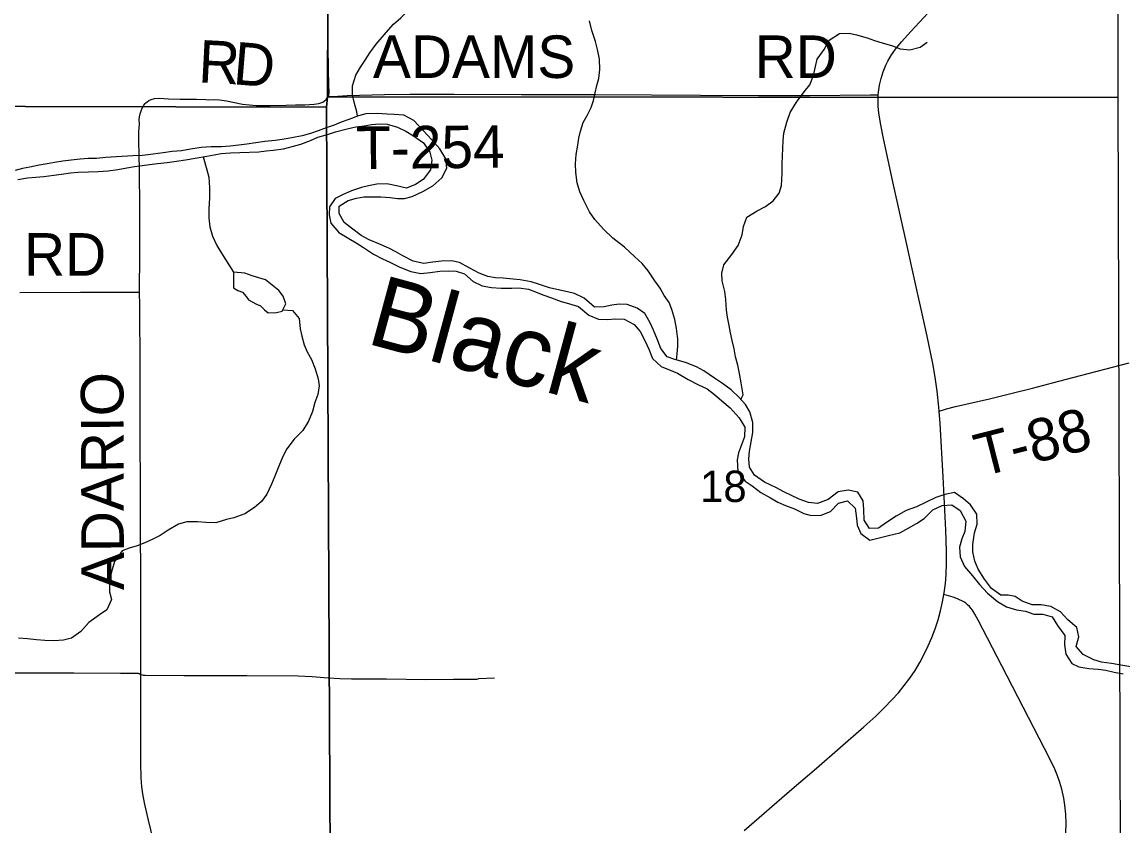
# Model space of a CAD drawing. Extents: x 0 to 70.2, y 0 to 31.4.
# Drawn here: x 4.299 to 5.768, y 15.356 to 16.429 of the extents above; entities that cross this region are included whole.
import ezdxf

# ---------------------------------------------------------------- set-up
doc = ezdxf.new("R2010")
doc.units = 0
for name, color, linetype in [('GM_X_County_Road', 7, 'Continuous'), ('GM_X_Major_River', 7, 'Continuous'), ('GM_X_Major_River_Text', 7, 'Continuous'), ('GM_X_Minor_Lake', 7, 'Continuous'), ('GM_X_Minor_River', 7, 'Continuous'), ('GM_X_Section', 7, 'Continuous'), ('GM_X_Section_Text', 7, 'Continuous'), ('GM_X_State_Route', 7, 'Continuous'), ('GM_X_Township_Road', 7, 'Continuous'), ('GM_X_Township_Road_Text', 7, 'Continuous')]:
    doc.layers.add(name, color=color, linetype=linetype)

msp = doc.modelspace()

# ---------------------------------------------------------------- linework, layer by layer
at = {"layer": 'GM_X_County_Road'}
msp.add_lwpolyline([(5.6936, 15.3452), (5.6937, 15.3577), (5.6933, 15.3701), (5.6921, 15.3825), (5.6907, 15.3916), (5.6879, 15.4038), (5.6853, 15.4128), (5.6822, 15.4216), (5.6786, 15.4303), (5.6719, 15.4443), (5.6576, 15.472), (5.6078, 15.5686), (5.5765, 15.6294), (5.5721, 15.6376), (5.5686, 15.6429), (5.5667, 15.6454), (5.5646, 15.6478), (5.5623, 15.65), (5.5598, 15.652), (5.5572, 15.6538), (5.5545, 15.6554), (5.5516, 15.6568), (5.5487, 15.658), (5.5428, 15.6601), (5.5367, 15.6618), (5.5304, 15.6636)], dxfattribs=at)
at = {"layer": 'GM_X_Major_River'}
for points in [[(5.3169, 15.8008), (5.3063, 15.8069), (5.2911, 15.8137), (5.2778, 15.8232), (5.271, 15.8338), (5.2699, 15.8452), (5.271, 15.8554), (5.2733, 15.8679), (5.2752, 15.8804), (5.2752, 15.8937), (5.2714, 15.9078), (5.2654, 15.9176), (5.2567, 15.9275), (5.2464, 15.937), (5.2347, 15.9457), (5.2241, 15.9529), (5.2101, 15.9627), (5.2002, 15.9681), (5.1854, 15.9737), (5.1714, 15.9775), (5.1608, 15.9813), (5.1525, 15.9923), (5.1479, 16.0041), (5.1426, 16.017), (5.1381, 16.0268), (5.1312, 16.039), (5.121, 16.0462), (5.1074, 16.0511), (5.0968, 16.0515), (5.0869, 16.0504), (5.077, 16.0481), (5.0638, 16.0477), (5.0501, 16.0595), (5.0372, 16.0659), (5.0278, 16.0682), (5.0134, 16.0712), (5.0039, 16.0735), (4.9891, 16.0784), (4.9792, 16.0814), (4.9648, 16.0841), (4.9554, 16.0852), (4.9417, 16.0864), (4.9319, 16.0868), (4.9213, 16.0886), (4.9099, 16.0932), (4.8966, 16.1), (4.8837, 16.1072), (4.8731, 16.1095), (4.8595, 16.1091), (4.8481, 16.1076), (4.836, 16.1061), (4.8216, 16.1091), (4.8079, 16.1163), (4.7984, 16.1216), (4.789, 16.1266), (4.7757, 16.1323), (4.7628, 16.1376), (4.7522, 16.1432), (4.7393, 16.1531), (4.7295, 16.1607), (4.7227, 16.1728), (4.7227, 16.1827), (4.7348, 16.1899), (4.7462, 16.1933), (4.756, 16.1948), (4.7655, 16.1952), (4.7784, 16.1952), (4.7909, 16.1941), (4.8008, 16.1929), (4.8102, 16.1929), (4.8205, 16.1956), (4.8345, 16.202), (4.8478, 16.2096), (4.8599, 16.2203), (4.8667, 16.2335), (4.8652, 16.2457), (4.8573, 16.2593), (4.8467, 16.2711), (4.8349, 16.2836), (4.8228, 16.2969), (4.8092, 16.3041), (4.7963, 16.3048), (4.7868, 16.3056), (4.7735, 16.3064), (4.7587, 16.306), (4.7489, 16.3033), (4.7356, 16.2984), (4.7257, 16.2946), (4.7163, 16.2908), (4.7053, 16.287), (4.6947, 16.2832), (4.6844, 16.2794), (4.6734, 16.2764), (4.6598, 16.2737), (4.6469, 16.2718), (4.6374, 16.2703), (4.6234, 16.2688), (4.5995, 16.2654), (4.5889, 16.2642), (4.5775, 16.2627), (4.5658, 16.2619)], [(4.546, 16.2494), (4.5559, 16.2513), (4.5654, 16.2528), (4.5779, 16.2536), (4.59, 16.2544), (4.6158, 16.2551), (4.6253, 16.2566), (4.6347, 16.2574), (4.6484, 16.2593), (4.6617, 16.2627), (4.6715, 16.2654), (4.6848, 16.2703), (4.6943, 16.2745), (4.7075, 16.2783), (4.7178, 16.2817), (4.7318, 16.2855), (4.7451, 16.2885), (4.7564, 16.29), (4.7659, 16.2916), (4.7769, 16.2927), (4.7872, 16.2923), (4.8008, 16.2881), (4.8118, 16.2828), (4.822, 16.2764), (4.8353, 16.2673), (4.844, 16.2548), (4.8467, 16.2438), (4.8447, 16.2309), (4.8349, 16.218), (4.825, 16.2115), (4.8129, 16.2066), (4.7996, 16.2096), (4.7864, 16.2123), (4.7731, 16.2119), (4.7621, 16.2096), (4.7526, 16.2074), (4.7393, 16.2032), (4.7272, 16.1979), (4.7174, 16.1929), (4.7101, 16.1816), (4.7094, 16.1709), (4.7117, 16.1599), (4.7226, 16.1474), (4.7359, 16.1395), (4.7458, 16.1334), (4.7552, 16.1273), (4.7689, 16.1182), (4.7806, 16.1121), (4.7905, 16.1076), (4.8041, 16.1012), (4.8185, 16.0951), (4.8318, 16.0928), (4.8443, 16.094), (4.8572, 16.0958), (4.8693, 16.0962), (4.8792, 16.0955), (4.8905, 16.0921), (4.9019, 16.0818), (4.914, 16.0761), (4.9265, 16.0739), (4.9394, 16.0731), (4.9535, 16.0731), (4.9629, 16.0735), (4.9758, 16.0716), (4.9853, 16.0682), (4.9948, 16.064), (5.0065, 16.0602), (5.0194, 16.0553), (5.0293, 16.0526), (5.0425, 16.0485), (5.0562, 16.0371), (5.0691, 16.0314), (5.0816, 16.031), (5.0911, 16.0321), (5.1036, 16.0318), (5.1168, 16.0246), (5.1248, 16.0151), (5.1312, 16.0029), (5.1365, 15.9916), (5.1415, 15.9791), (5.1528, 15.9684), (5.1649, 15.9635), (5.1748, 15.9593), (5.1888, 15.951), (5.2021, 15.9445), (5.2142, 15.9385), (5.2244, 15.9309), (5.2339, 15.9225), (5.2449, 15.9131), (5.257, 15.8998), (5.2646, 15.8873), (5.2642, 15.8744), (5.2601, 15.8638), (5.2563, 15.8531), (5.2544, 15.8437), (5.2555, 15.8281), (5.265, 15.8152), (5.2744, 15.8088), (5.2862, 15.8), (5.2991, 15.7928), (5.3089, 15.7871)], [(4.5658, 16.2619), (4.5521, 16.2619), (4.5385, 16.2608), (4.5244, 16.2585), (4.5123, 16.2566), (4.4998, 16.2555), (4.488, 16.254), (4.4744, 16.2521), (4.46, 16.2502), (4.4475, 16.2498), (4.4255, 16.2483), (4.4111, 16.2475), (4.3986, 16.2464), (4.3876, 16.246), (4.377, 16.2452), (4.3648, 16.2441), (4.3538, 16.2426), (4.3425, 16.2407), (4.333, 16.2392), (4.322, 16.2373), (4.3099, 16.2346), (4.3, 16.2327), (4.2901, 16.2301)], [(4.2936, 16.2183), (4.3068, 16.2202), (4.3178, 16.2213), (4.3284, 16.2221), (4.3417, 16.224), (4.3519, 16.2255), (4.3641, 16.227), (4.3743, 16.2278), (4.3883, 16.2282), (4.4012, 16.2289), (4.4145, 16.2297), (4.4274, 16.2316), (4.4395, 16.2339), (4.4497, 16.2354), (4.4596, 16.2369), (4.4695, 16.238), (4.4801, 16.2396), (4.493, 16.2411), (4.5055, 16.2426), (4.5176, 16.2445), (4.5305, 16.2468), (4.546, 16.2494)], [(5.7804, 15.5672), (5.7668, 15.5695), (5.7543, 15.5717), (5.741, 15.5736), (5.7308, 15.5763), (5.7164, 15.5835), (5.7073, 15.5941), (5.7107, 15.607), (5.708, 15.6195), (5.6963, 15.6298), (5.6861, 15.6408), (5.6732, 15.6476), (5.6607, 15.6499), (5.6485, 15.6499), (5.6353, 15.6548), (5.6258, 15.6612), (5.6163, 15.6628), (5.6068, 15.6628), (5.594, 15.6719), (5.5849, 15.6844), (5.5765, 15.6976), (5.572, 15.7083), (5.5693, 15.7208), (5.5693, 15.7306), (5.5716, 15.7462), (5.575, 15.7576), (5.5747, 15.7709), (5.5663, 15.7834), (5.5569, 15.7917), (5.5447, 15.8001), (5.5318, 15.7974), (5.5197, 15.7932), (5.4939, 15.7811), (5.4803, 15.7758), (5.4666, 15.7682), (5.4541, 15.7598), (5.4431, 15.7526), (5.431, 15.7519), (5.4242, 15.7629), (5.4238, 15.7773), (5.4227, 15.7887), (5.4155, 15.8004), (5.4026, 15.8031), (5.3893, 15.8008), (5.376, 15.7909), (5.3616, 15.7852), (5.3499, 15.7868), (5.3374, 15.7913), (5.3271, 15.7959), (5.3169, 15.8008)], [(5.3089, 15.7871), (5.3188, 15.7826), (5.3309, 15.778), (5.3434, 15.772), (5.3533, 15.7693), (5.3665, 15.7697), (5.379, 15.7746), (5.3897, 15.786), (5.4018, 15.789), (5.412, 15.7792), (5.4139, 15.7659), (5.4147, 15.7564), (5.4196, 15.7454), (5.4317, 15.7363), (5.4458, 15.7401), (5.4568, 15.7428), (5.4715, 15.7462), (5.4837, 15.753), (5.4939, 15.7587), (5.5042, 15.7655), (5.5159, 15.7769), (5.5284, 15.7826), (5.5413, 15.7837), (5.5523, 15.7758), (5.5599, 15.7617), (5.5587, 15.7481), (5.5546, 15.7382), (5.5515, 15.7272), (5.5523, 15.7143), (5.558, 15.7014), (5.5689, 15.6885), (5.578, 15.6772), (5.589, 15.6654), (5.6023, 15.6544), (5.6144, 15.6472), (5.6277, 15.6434), (5.6394, 15.6415), (5.6508, 15.6377), (5.6629, 15.6377), (5.6751, 15.6339), (5.6823, 15.6222), (5.6921, 15.6089), (5.6917, 15.5964), (5.6936, 15.5842), (5.7016, 15.5717), (5.711, 15.5672), (5.7243, 15.5649), (5.7364, 15.5641), (5.7467, 15.5626), (5.7581, 15.56), (5.7698, 15.5577)]]:
    msp.add_lwpolyline(points, dxfattribs=at)
at = {"layer": 'GM_X_Minor_Lake'}
for points in [[(4.5817, 16.0733), (4.5877, 16.0698), (4.5938, 16.0675), (4.5986, 16.0618), (4.602, 16.0572), (4.6126, 16.0518), (4.6179, 16.0494), (4.6231, 16.0441), (4.628, 16.0399), (4.639, 16.0405), (4.6466, 16.0424), (4.6516, 16.0522), (4.6479, 16.0621), (4.6423, 16.0701), (4.6333, 16.077), (4.6243, 16.0843), (4.6065, 16.0894), (4.5967, 16.0929), (4.5819, 16.0945)], [(4.5819, 16.0945), (4.5817, 16.0733)]]:
    msp.add_lwpolyline(points, dxfattribs=at)
at = {"layer": 'GM_X_Minor_River'}
for points in [[(4.7472, 16.3027), (4.7466, 16.3086), (4.7428, 16.3215), (4.7409, 16.3314), (4.7409, 16.3435), (4.7451, 16.3576), (4.7512, 16.3682), (4.7576, 16.3777), (4.7637, 16.3875), (4.7724, 16.3989), (4.7857, 16.4145), (4.7956, 16.4255), (4.8054, 16.4342), (4.8168, 16.4456)], [(5.1736, 15.9769), (5.1741, 15.9851), (5.1752, 15.9954), (5.1752, 16.0048), (5.1733, 16.0189), (5.1714, 16.031), (5.1673, 16.0443), (5.1635, 16.0538), (5.157, 16.0633), (5.1514, 16.0731), (5.1445, 16.083), (5.1354, 16.0963), (5.1275, 16.1061), (5.118, 16.1148), (5.104, 16.1277), (5.0885, 16.1399), (5.076, 16.1516), (5.0642, 16.1649), (5.0574, 16.1751), (5.0498, 16.1899), (5.0441, 16.2017), (5.0407, 16.2138), (5.0388, 16.2275), (5.0385, 16.2392), (5.0392, 16.2514), (5.0415, 16.2639), (5.043, 16.2734), (5.0453, 16.2829), (5.0487, 16.2942), (5.054, 16.3037), (5.0594, 16.3143), (5.0624, 16.3238), (5.0647, 16.3341), (5.067, 16.3436), (5.0696, 16.353), (5.0711, 16.3652), (5.0708, 16.3788), (5.0677, 16.3917), (5.0651, 16.4027), (5.0602, 16.4171), (5.0571, 16.43)], [(5.2595, 15.9242), (5.2624, 15.9305), (5.2597, 15.9464), (5.2574, 15.959), (5.2552, 15.97), (5.2522, 15.9813), (5.2503, 15.992), (5.248, 16.0033), (5.2457, 16.0132), (5.2438, 16.0231), (5.2416, 16.0341), (5.2404, 16.0435), (5.2393, 16.058), (5.2378, 16.0686), (5.2344, 16.0826), (5.234, 16.0929), (5.2367, 16.1042), (5.2473, 16.1179), (5.2556, 16.13), (5.2613, 16.1441), (5.2629, 16.1554), (5.2674, 16.168), (5.2811, 16.1763), (5.2921, 16.182), (5.3027, 16.1896), (5.3106, 16.1998), (5.3137, 16.2101), (5.3145, 16.226), (5.3145, 16.2393), (5.3152, 16.2499), (5.3156, 16.2594), (5.316, 16.2704), (5.3168, 16.2799), (5.3206, 16.2946), (5.3251, 16.3075), (5.3335, 16.3216), (5.3441, 16.3352), (5.3513, 16.3447), (5.3562, 16.3569), (5.3593, 16.369), (5.3615, 16.3789), (5.3707, 16.3918), (5.3775, 16.4043), (5.3911, 16.413), (5.404, 16.4138), (5.4139, 16.4115), (5.4283, 16.4073), (5.4378, 16.4039), (5.448, 16.4009), (5.462, 16.3967), (5.4723, 16.3929), (5.4851, 16.3914), (5.4988, 16.3948), (5.5083, 16.4016)], [(4.5412, 16.2486), (4.5461, 16.231), (4.549, 16.2212), (4.5496, 16.2071), (4.5495, 16.1931), (4.549, 16.1794), (4.5489, 16.1669), (4.5503, 16.1551), (4.5539, 16.1426), (4.5595, 16.13), (4.5655, 16.1197), (4.5819, 16.0945)], [(4.6475, 16.0442), (4.6606, 16.043), (4.6696, 16.0327), (4.671, 16.0186), (4.6728, 16.0087), (4.6761, 15.9973), (4.6802, 15.9878), (4.6858, 15.9775), (4.691, 15.9653), (4.695, 15.952), (4.6961, 15.9425), (4.6944, 15.9308), (4.6905, 15.9202), (4.6874, 15.9084), (4.682, 15.8952), (4.6742, 15.8828), (4.6628, 15.8715), (4.6528, 15.8583), (4.6478, 15.8481), (4.6423, 15.8353), (4.6369, 15.8217), (4.6326, 15.8111), (4.6264, 15.7979), (4.6191, 15.7881), (4.6096, 15.7798), (4.597, 15.7716), (4.5821, 15.766), (4.5722, 15.7638), (4.5582, 15.7594), (4.5449, 15.7599), (4.5335, 15.7608), (4.5195, 15.7609), (4.5081, 15.7576), (4.4944, 15.7497), (4.4837, 15.7426), (4.4738, 15.7378), (4.4635, 15.733), (4.4529, 15.7289), (4.4426, 15.7256), (4.4331, 15.7222), (4.4227, 15.7079), (4.4188, 15.6939), (4.416, 15.6822), (4.4162, 15.6674), (4.4188, 15.6571), (4.4126, 15.6431), (4.4027, 15.6364), (4.3885, 15.6263), (4.3778, 15.6142), (4.3652, 15.6056), (4.3549, 15.6027), (4.342, 15.6017), (4.3299, 15.6025), (4.3186, 15.6034), (4.3064, 15.6047), (4.2947, 15.6055)]]:
    msp.add_lwpolyline(points, dxfattribs=at)
at = {"layer": 'GM_X_Section'}
for points in [[(4.7109, 17.3315), (5.7641, 17.3372), (5.7628, 16.3276), (4.7073, 16.3287)], [(3.7116, 17.3342), (4.7109, 17.3315), (4.7073, 16.3287), (4.7058, 16.315), (3.7004, 16.3169)], [(4.7073, 16.3287), (5.7628, 16.3276), (5.7658, 15.3168), (4.7107, 15.313), (4.7058, 16.315)], [(3.7004, 16.3169), (4.7058, 16.315), (4.7107, 15.313), (4.7107, 15.3013), (3.6966, 15.3051)]]:
    msp.add_lwpolyline(points, close=True, dxfattribs=at)
at = {"layer": 'GM_X_State_Route'}
for points in [[(5.4875, 16.1027), (5.4821, 16.1272), (5.4625, 16.2152), (5.4499, 16.2729), (5.4463, 16.2912), (5.4438, 16.3066), (5.4429, 16.316), (5.4426, 16.3253), (5.4429, 16.3312), (5.4431, 16.3347), (5.4445, 16.344), (5.4467, 16.3532), (5.4496, 16.3621), (5.4531, 16.3708), (5.4559, 16.3764), (5.4606, 16.3845), (5.466, 16.3923), (5.4738, 16.402), (5.4862, 16.416), (5.5326, 16.4662)], [(5.3604, 15.4317), (5.4237, 15.4868), (5.4398, 15.5014), (5.4509, 15.5122), (5.4617, 15.5233), (5.4699, 15.5326), (5.4777, 15.5422), (5.4851, 15.5521), (5.492, 15.5624), (5.4984, 15.573), (5.5043, 15.5839), (5.5096, 15.5951), (5.5145, 15.6065), (5.5188, 15.6181), (5.5227, 15.6299), (5.526, 15.6418), (5.5288, 15.6538), (5.5304, 15.6636), (5.5309, 15.666), (5.5325, 15.6783), (5.5336, 15.6907), (5.5342, 15.7062), (5.5342, 15.7217), (5.5332, 15.7496), (5.5296, 15.821), (5.5258, 15.8924), (5.5244, 15.9089), (5.524, 15.914), (5.5216, 15.9356), (5.5189, 15.954), (5.5157, 15.9723), (5.5081, 16.0088), (5.4875, 16.1027)], [(5.264, 15.3484), (5.3273, 15.4035), (5.3604, 15.4317)]]:
    msp.add_lwpolyline(points, dxfattribs=at)
at = {"layer": 'GM_X_Township_Road'}
for p, q in [((4.4559, 16.251), (4.4555, 16.2698)), ((4.4561, 16.2312), (4.4559, 16.251))]:
    msp.add_line(p, q, dxfattribs=at)
for points in [[(4.7083, 16.3291), (4.7089, 16.3302), (4.7095, 16.3339), (4.7094, 16.3372), (4.7093, 16.342), (4.7084, 16.3938), (4.7077, 16.5212), (4.7083, 16.5865), (4.7101, 16.6826), (4.7103, 16.7321), (4.7101, 16.7694), (4.7103, 16.8222), (4.7103, 16.831)], [(4.4555, 16.2698), (4.4553, 16.2758), (4.4553, 16.2818), (4.456, 16.2925), (4.4558, 16.2978), (4.4561, 16.3017), (4.4571, 16.3058), (4.4583, 16.3098), (4.4598, 16.3136), (4.462, 16.3173), (4.4639, 16.3196), (4.4648, 16.3204), (4.4664, 16.322), (4.4688, 16.3237), (4.4719, 16.3252), (4.4761, 16.3264), (4.4826, 16.3267), (4.4951, 16.3259), (4.5105, 16.3257), (4.5323, 16.3254), (4.5447, 16.3251), (4.5477, 16.3248), (4.557, 16.325), (4.5632, 16.3245), (4.5725, 16.3232), (4.5938, 16.319), (4.603, 16.3177), (4.6122, 16.3171), (4.6306, 16.3169), (4.6523, 16.3175), (4.6647, 16.3177), (4.6772, 16.318), (4.6894, 16.3188), (4.6955, 16.3196), (4.6982, 16.3204), (4.7009, 16.3216), (4.7033, 16.3233), (4.7055, 16.3252), (4.7074, 16.3275), (4.7083, 16.3291)], [(4.7083, 16.3291), (4.7213, 16.3297), (4.7337, 16.3303), (4.7833, 16.3316), (4.8174, 16.3321), (4.8763, 16.3322), (4.9664, 16.3319), (5.0192, 16.3318), (5.0657, 16.3315), (5.1402, 16.3313), (5.2054, 16.3308), (5.2831, 16.3304), (5.3514, 16.3305), (5.4321, 16.3311), (5.4429, 16.3312)], [(4.4564, 16.0675), (4.4564, 16.0717), (4.4567, 16.1147), (4.4567, 16.1547), (4.4567, 16.1795), (4.4561, 16.2312)], [(4.2963, 16.0674), (4.3772, 16.0676), (4.4487, 16.0675), (4.4564, 16.0675)], [(4.4579, 15.5571), (4.4578, 15.5622), (4.4578, 15.6026), (4.4579, 15.6989), (4.4577, 15.7393), (4.4577, 15.8014), (4.4572, 15.8791), (4.4572, 15.9661), (4.4565, 16.05), (4.4564, 16.0675)], [(5.5244, 15.9089), (5.5313, 15.9109), (5.5342, 15.9118), (5.5462, 15.915), (5.5916, 15.9252), (5.6217, 15.9327), (5.6488, 15.9396), (5.6758, 15.9467), (5.7028, 15.9537), (5.778, 15.9731)], [(4.2786, 15.5593), (4.3687, 15.5593), (4.4308, 15.5589), (4.451, 15.5589), (4.4524, 15.5589), (4.4534, 15.5588), (4.4543, 15.5587), (4.4557, 15.5582), (4.4579, 15.5571), (4.4602, 15.5564), (4.4613, 15.5562), (4.4626, 15.556), (4.4637, 15.5559), (4.5155, 15.5557), (4.5995, 15.5556), (4.6679, 15.5549), (4.6866, 15.5541), (4.7083, 15.5526), (4.7238, 15.5514), (4.7393, 15.5509), (4.7859, 15.5509), (4.8387, 15.5502), (4.8757, 15.5506), (4.8818, 15.5505), (4.898, 15.5505), (4.9069, 15.5508), (4.9084, 15.551), (4.9094, 15.5514), (4.9305, 15.5526)], [(4.4843, 14.7998), (4.4844, 14.808), (4.4851, 14.867), (4.4857, 14.9384), (4.4859, 14.9881), (4.4855, 15.0347), (4.4852, 15.1093), (4.4852, 15.187), (4.4857, 15.2585), (4.4854, 15.2741), (4.4849, 15.2876), (4.4844, 15.2924), (4.484, 15.2958), (4.4824, 15.3039), (4.4817, 15.3073), (4.4678, 15.364), (4.4629, 15.3853), (4.4605, 15.3975), (4.4592, 15.4068), (4.4583, 15.4192), (4.4579, 15.4379), (4.4579, 15.5571)]]:
    msp.add_lwpolyline(points, dxfattribs=at)

# ---------------------------------------------------------------- texts
at = {"layer": 'GM_X_Major_River_Text'}
msp.add_text('Black', height=0.09473, rotation=344.8507, dxfattribs=at).set_placement((4.757, 15.9998))
at = {"layer": 'GM_X_Section_Text'}
msp.add_text('18', height=0.04186, rotation=0, dxfattribs=at).set_placement((5.2049, 15.7874))
at = {"layer": 'GM_X_Township_Road_Text'}
for s, height, rotation, p in [('ADAMS', 0.05682, 0.0007, (4.768, 16.3538)), ('R', 0.0568, 357.0168, (4.534, 16.348)), ('D', 0.0568, 355.2297, (4.5801, 16.3456)), ('RD', 0.05682, 0, (5.2778, 16.3538)), ('T-254', 0.05682, 0.545, (4.7457, 16.2321)), ('RD', 0.05682, 0, (4.302, 16.0897)), ('ADARIO', 0.05682, 90.1709, (4.4355, 15.6697)), ('T-88', 0.05682, 14.2925, (5.5803, 15.8209))]:
    msp.add_text(s, height=height, rotation=rotation, dxfattribs=at).set_placement(p)

doc.saveas('drawing.dxf')
